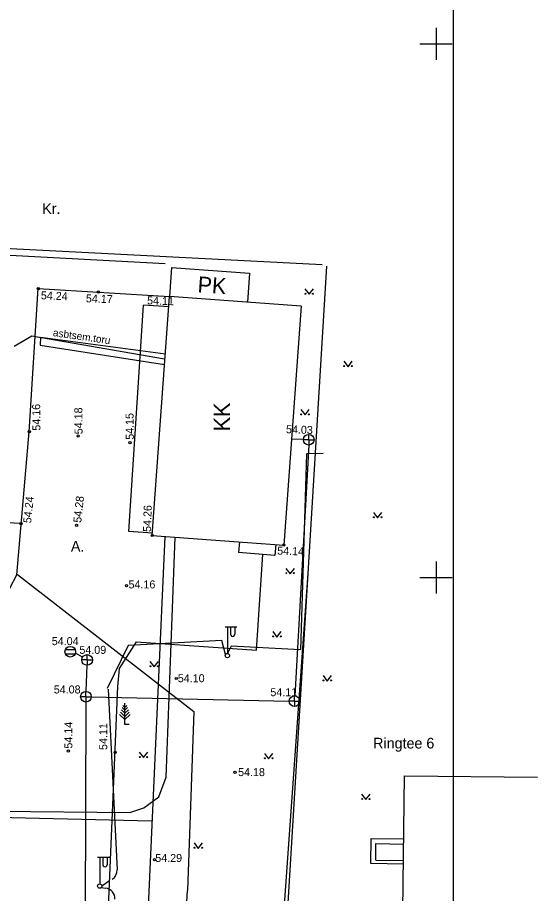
# Model space of a CAD drawing. Extents: x 9156 to 9809, y 2728 to 4000.
# Drawn here: x 9760.8 to 9809.5, y 3770.4 to 3852.5 of the extents above; entities that cross this region are included whole.
import ezdxf

# ---------------------------------------------------------------- set-up
doc = ezdxf.new("R2010")
doc.units = 0
doc.layers.add('Level 54', color=7, linetype='Continuous')
doc.layers.add('Level 63', color=7, linetype='Continuous')

msp = doc.modelspace()

# ---------------------------------------------------------------- linework, layer by layer
at = {"layer": 'Level 54'}
for p, q in [((9800, 3851.5), (9800, 3848.5)), ((9798.5, 3850), (9801.5, 3850)), ((9789.351, 3829.312), (9721.45, 3832.75)), ((9774.65, 3829.399), (9721.689, 3832.211)), ((9775.251, 3829.052), (9775.054, 3826.325)), ((9775.251, 3829.052), (9782.553, 3828.526)), ((9785.171, 3753.397), (9789.782, 3829.186)), ((9782.553, 3828.526), (9782.356, 3825.799)), ((9787.723, 3827.043), (9788.126, 3826.538)), ((9788.126, 3826.538), (9788.523, 3827.043)), ((9773.44, 3803.946), (9775.054, 3826.325)), ((9787.383, 3825.436), (9775.054, 3826.325)), ((9771.24, 3804.309), (9772.628, 3825.535)), ((9774.992, 3825.38), (9772.628, 3825.535)), ((9787.383, 3825.436), (9785.759, 3803.053)), ((9762.172, 3822.627), (9760.496, 3821.643)), ((9774.595, 3820.462), (9762.172, 3822.627)), ((9762.982, 3822.486), (9762.958, 3821.788)), ((9774.661, 3820.945), (9762.982, 3822.486)), ((9762.958, 3821.788), (9774.593, 3819.968)), ((9791.362, 3820.263), (9791.765, 3819.758)), ((9791.765, 3819.758), (9792.162, 3820.263)), ((9787.333, 3815.741), (9787.736, 3815.235)), ((9787.736, 3815.235), (9788.133, 3815.741)), ((9788.082, 3812.915), (9788.082, 3813.415)), ((9787.588, 3812.924), (9786.49, 3812.959)), ((9788.093, 3812.411), (9786.784, 3788.927)), ((9788.082, 3812.915), (9787.582, 3812.915)), ((9788.082, 3812.915), (9788.582, 3812.915)), ((9788.082, 3812.915), (9788.082, 3812.415)), ((9787.876, 3811.582), (9787.321, 3793.239)), ((9789.439, 3811.633), (9787.876, 3811.582)), ((9794.133, 3806.098), (9794.536, 3805.593)), ((9794.536, 3805.593), (9794.933, 3806.098)), ((9773.454, 3804.164), (9771.24, 3804.309)), ((9774.628, 3803.86), (9769.636, 3693.047)), ((9773.44, 3803.946), (9785.759, 3803.053)), ((9774.753, 3781.295), (9775.591, 3803.79)), ((9781.592, 3803.348), (9781.516, 3802.342)), ((9784.922, 3802.082), (9781.516, 3802.342)), ((9785.001, 3803.11), (9784.922, 3802.082)), ((9783.209, 3793.213), (9783.79, 3802.169)), ((9785.938, 3800.869), (9786.341, 3800.364)), ((9786.341, 3800.364), (9786.738, 3800.869)), ((9800, 3801.5), (9800, 3798.5)), ((9760.823, 3800.283), (9777.34, 3787.453)), ((9784.66, 3753.508), (9788.046, 3800.39)), ((9798.5, 3800), (9801.5, 3800)), ((9780.269, 3795.399), (9781.369, 3795.399)), ((9780.469, 3795.399), (9780.469, 3792.899)), ((9780.769, 3795.399), (9780.769, 3794.699)), ((9781.169, 3795.399), (9781.169, 3794.699)), ((9784.71, 3794.941), (9785.113, 3794.436)), ((9785.113, 3794.436), (9785.51, 3794.941)), ((9771.19, 3793.643), (9769.2, 3789.598)), ((9779.965, 3794.098), (9771.19, 3793.643)), ((9780.292, 3792.792), (9779.965, 3794.098)), ((9780.819, 3793.592), (9780.469, 3792.899)), ((9787.321, 3793.239), (9780.819, 3793.592)), ((9765.307, 3793.263), (9766.223, 3793.263)), ((9765.307, 3792.863), (9766.223, 3792.863)), ((9766.906, 3792.539), (9766.255, 3792.93)), ((9767.336, 3792.288), (9767.336, 3792.788)), ((9767.336, 3792.288), (9766.836, 3792.288)), ((9767.236, 3789.349), (9767.336, 3791.788)), ((9767.336, 3792.288), (9767.836, 3792.288)), ((9767.336, 3792.288), (9767.336, 3791.788)), ((9773.218, 3792.145), (9773.621, 3791.639)), ((9773.621, 3791.639), (9774.018, 3792.145)), ((9789.423, 3790.822), (9789.826, 3790.316)), ((9789.826, 3790.316), (9790.223, 3790.822)), ((9767.228, 3788.846), (9767.228, 3789.346)), ((9769.311, 3789.552), (9770.147, 3772.631)), ((9767.228, 3788.846), (9766.728, 3788.846)), ((9767.228, 3788.846), (9767.728, 3788.846)), ((9767.228, 3788.846), (9767.228, 3788.346)), ((9767.723, 3788.824), (9786.263, 3788.429)), ((9786.753, 3788.425), (9786.253, 3788.425)), ((9786.753, 3788.425), (9786.753, 3788.925)), ((9786.753, 3788.425), (9787.253, 3788.425)), ((9786.753, 3788.425), (9786.753, 3787.925)), ((9767.154, 3760.265), (9767.24, 3788.334)), ((9770.875, 3787.298), (9770.545, 3787.628)), ((9770.875, 3787.598), (9770.627, 3787.847)), ((9770.875, 3787.848), (9770.694, 3788.029)), ((9770.875, 3786.248), (9770.875, 3788.248)), ((9770.875, 3787.848), (9771.056, 3788.029)), ((9770.875, 3787.598), (9771.124, 3787.847)), ((9770.875, 3787.298), (9771.205, 3787.628)), ((9770.875, 3786.698), (9770.383, 3787.19)), ((9770.875, 3786.998), (9770.464, 3787.409)), ((9770.875, 3786.998), (9771.286, 3787.409)), ((9770.875, 3786.698), (9771.367, 3787.19)), ((9777.34, 3787.453), (9776.735, 3770.687)), ((9771.275, 3786.248), (9770.875, 3786.248)), ((9772.214, 3783.644), (9772.617, 3783.139)), ((9772.617, 3783.139), (9773.014, 3783.644)), ((9783.929, 3783.532), (9784.332, 3783.027)), ((9784.332, 3783.027), (9784.729, 3783.532)), ((9774.057, 3779.476), (9774.753, 3781.295)), ((9772.662, 3778.427), (9774.057, 3779.476)), ((9793.025, 3779.712), (9793.428, 3779.206)), ((9793.428, 3779.206), (9793.825, 3779.712)), ((9754.992, 3778.18), (9771.338, 3778.007)), ((9771.338, 3778.007), (9772.662, 3778.427)), ((9754.938, 3777.667), (9773.35, 3777.214)), ((9793.899, 3773.211), (9793.928, 3775.558)), ((9793.928, 3775.558), (9796.989, 3775.519)), ((9777.346, 3775.143), (9777.749, 3774.638)), ((9777.749, 3774.638), (9778.146, 3775.143)), ((9794.357, 3773.546), (9794.376, 3775.08)), ((9794.376, 3775.08), (9796.983, 3775.047)), ((9768.319, 3773.805), (9769.419, 3773.805)), ((9768.519, 3773.805), (9768.519, 3771.305)), ((9768.819, 3773.805), (9768.819, 3773.105)), ((9769.219, 3773.805), (9769.219, 3773.105)), ((9796.959, 3773.172), (9793.899, 3773.211)), ((9794.357, 3773.546), (9796.963, 3773.513)), ((9769.447, 3771.582), (9768.719, 3771.105)), ((9768.66, 3770.963), (9769.077, 3770.909)), ((9772.838, 3695.211), (9776.735, 3770.688))]:
    msp.add_line(p, q, dxfattribs=at)
for points in [[(9719.899, 3797.776), (9722.054, 3797.827), (9755.91, 3796.132), (9758.747, 3796.52), (9760.758, 3800.246), (9761.928, 3813.669), (9762.764, 3827.074), (9775.054, 3826.325)], [(9761.151, 3805.057), (9726.67, 3806.73), (9726.384, 3802.733)], [(9770.211, 3789.798), (9770.369, 3791.486), (9771.974, 3794), (9783.209, 3793.213)], [(9767.422, 3706.742), (9767.572, 3708.712), (9764.558, 3731.978), (9771.571, 3731.778), (9772.74, 3757.064), (9768.845, 3757.295), (9770.211, 3789.798)], [(9796.678, 3751.167), (9797.064, 3781.422), (9809.499, 3781.315)]]:
    msp.add_lwpolyline(points, dxfattribs=at)
for centre, radius in [((9762.764, 3827.074), 0.102), ((9768.392, 3826.762), 0.102), ((9787.773, 3826.593), 0.0428), ((9788.473, 3826.593), 0.0452), ((9791.412, 3819.813), 0.0428), ((9792.112, 3819.813), 0.0452), ((9787.383, 3815.291), 0.0428), ((9788.083, 3815.291), 0.0452), ((9761.928, 3813.669), 0.102), ((9766.498, 3813.267), 0.102), ((9788.082, 3812.915), 0.5), ((9771.35, 3812.645), 0.102), ((9794.183, 3805.648), 0.0428), ((9794.883, 3805.648), 0.0452), ((9761.151, 3805.057), 0.102), ((9766.351, 3804.898), 0.102), ((9773.44, 3803.946), 0.102), ((9785.759, 3803.053), 0.102), ((9785.988, 3800.419), 0.0428), ((9786.688, 3800.419), 0.0452), ((9771.025, 3799.239), 0.102), ((9784.76, 3794.491), 0.0428), ((9785.46, 3794.491), 0.0452), ((9765.765, 3793.063), 0.5), ((9767.336, 3792.288), 0.5), ((9780.469, 3792.699), 0.2), ((9773.268, 3791.695), 0.0428), ((9773.968, 3791.695), 0.0452), ((9775.681, 3790.556), 0.102), ((9789.473, 3790.372), 0.0428), ((9790.173, 3790.372), 0.0452), ((9767.228, 3788.846), 0.5), ((9786.753, 3788.425), 0.5), ((9765.58, 3783.753), 0.102), ((9769.965, 3783.636), 0.102), ((9772.264, 3783.194), 0.0428), ((9772.964, 3783.194), 0.0452), ((9783.979, 3783.082), 0.0428), ((9784.679, 3783.082), 0.0452), ((9781.189, 3781.762), 0.102), ((9793.075, 3779.262), 0.0428), ((9793.775, 3779.262), 0.0452), ((9777.396, 3774.693), 0.0428), ((9778.096, 3774.693), 0.0452), ((9773.641, 3773.582), 0.102), ((9768.519, 3771.105), 0.2)]:
    msp.add_circle(centre, radius, dxfattribs=at)
for centre, radius, start, end in [((9780.969, 3794.699), 0.2, 179.93931, 0.0607), ((9769.019, 3773.104), 0.2, 179.93931, 0.0607), ((9769.149, 3772.582), 1, 303.2372, 2.82802), ((9768.945, 3769.918), 1, 357.38123, 82.62243)]:
    msp.add_arc(centre, radius, start, end, dxfattribs=at)
at = {"layer": 'Level 63'}
msp.add_lwpolyline([(9275.527, 3966.797), (9801.617, 3966.797), (9801.617, 3329.636), (9275.527, 3329.636)], close=True, dxfattribs=at)

# ---------------------------------------------------------------- texts
at = {"layer": 'Level 54'}
for s, height, p in [('Kr.', 1, (9763.137, 3834.064)), ('A.', 1, (9765.822, 3802.439)), ('54.16', 0.75, (9771.216, 3798.99)), ('54.04', 0.75, (9764.03, 3793.677)), ('54.09', 0.75, (9766.614, 3792.858)), ('54.10', 0.75, (9775.828, 3790.201)), ('54.08', 0.75, (9764.216, 3789.148)), ('54.11', 0.75, (9784.494, 3788.893)), ('Ringtee 6', 1, (9794.119, 3783.994)), ('54.18', 0.75, (9781.472, 3781.408)), ('54.29', 0.75, (9773.72, 3773.364))]:
    msp.add_text(s, height=height, dxfattribs=at).set_placement(p)
for s, height, rotation, p in [('PK', 1.5, 356.15434, (9777.647, 3826.727)), ('54.24', 0.75, 358.00165, (9762.999, 3826.071)), ('54.17', 0.75, 358.00165, (9767.213, 3825.792)), ('54.11', 0.75, 358.00165, (9772.94, 3825.601)), ('asbtsem.toru', 0.7, 351.84962, (9764.109, 3822.628)), ('KK', 1.5, 90, (9780.7, 3813.709)), ('54.16', 0.75, 90.66877, (9762.969, 3813.768)), ('54.18', 0.75, 90.66877, (9766.916, 3813.433)), ('54.15', 0.75, 90.66877, (9771.71, 3812.916)), ('54.03', 0.75, 358.00165, (9785.948, 3813.534)), ('54.24', 0.75, 83.87238, (9762.087, 3805.068)), ('54.28', 0.75, 83.87238, (9766.784, 3805.111)), ('54.26', 0.75, 88.21026, (9773.313, 3804.27)), ('54.14', 0.75, 358.00165, (9785.123, 3802.158)), ('54.14', 0.75, 90.11784, (9765.958, 3783.984)), ('54.11', 0.75, 89.73293, (9769.221, 3783.853))]:
    msp.add_text(s, height=height, rotation=rotation, dxfattribs=at).set_placement(p)

doc.saveas('drawing.dxf')
